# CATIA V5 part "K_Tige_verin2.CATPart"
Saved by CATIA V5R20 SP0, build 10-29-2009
Part number: Tige_verin2
Bounding box of the stored display mesh (mm): x -14 to 14, y 222.993 to 238.485, z 85.559 to 127.709
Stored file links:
  G:\Khaled_CFAO_2011\ST2M\ST2M_GR1\hgrenier\Khaled\CAD_ThinkMOTION\K_Tige_verin2.CATPart
  C:\Users\Tom\Documents\Cours 2A\CFAO\Projet thinkmotion\Hugo\porte_outil.CATProduct
  G:\Khaled_CFAO_2011\ST2M\ST2M_GR1\hgrenier\Khaled\CAD_ThinkMOTION\K_Squelette.CATPart
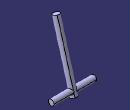
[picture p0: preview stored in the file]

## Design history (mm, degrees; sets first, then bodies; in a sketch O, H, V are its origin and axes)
Set1
  Plane1 "plan_sym": linked copy from another document
  Point1 "Centre_verin2/tête": linked copy from another document
  Point2 "Centre_godet/verin2": linked copy from another document
Body1 (main body)
  Sketch1 on Plane1, origin (0, 0, 0), H (0, 1, 0), V (0, 0, 1)
    axis line L1 (223.049, 133.683) -> (235.708, 89.158)
    point P1 (223.049, 133.683)
    point P2 (235.708, 89.158)
    reference projected point E1 (235.708, 89.158) from Point1
    reference projected point E2 (223.049, 133.683) from Point2
    line L2 (236.5769, 86.1018) -> (238.4929, 86.6465)
    point P3 (236.5769, 86.1018)
    line L3 (238.4929, 86.6465) -> (226.8176, 127.7114)
    line L4 (226.8176, 127.7114) -> (224.9017, 127.1667)
    line L5 (224.9017, 127.1667) -> (236.5769, 86.1018)
    coincidence: P2 E1, P1 E2, P3 L1
    perpendicularity: L2 L1, L2 L3
    parallelism: L5 L3, L2 L4
  Shaft1: profile Sketch1, axis Sketch1.L1, angle 360
  Sketch2 on Plane1, origin (0, 0, 0), H (0, 1, 0), V (0, 0, 1)
    circle A1 centre (235.708, 89.158) radius 1.8457
    point P1 (235.708, 89.158)
    reference projected point E1 (235.708, 89.158) from Point1
    radius A1 = 1.8457
    coincidence: P1 E1
  Pad1: profile Sketch2, direction (1, 0, 0), length 14, mirrored extent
